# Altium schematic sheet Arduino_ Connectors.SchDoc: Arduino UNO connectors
size A4; Date: 25-FEB-2015; Author: A.B; CompanyName: STMicroelectronics; Address1: 12, Rue Jules HOROWITZ; Address2: 38019 Grenoble; Address3: FRANCE; DocumentNumber: MB1191; Revision: B-02; SheetNumber: 6; SheetTotal: 13; Project: STM32F746G-DISCO
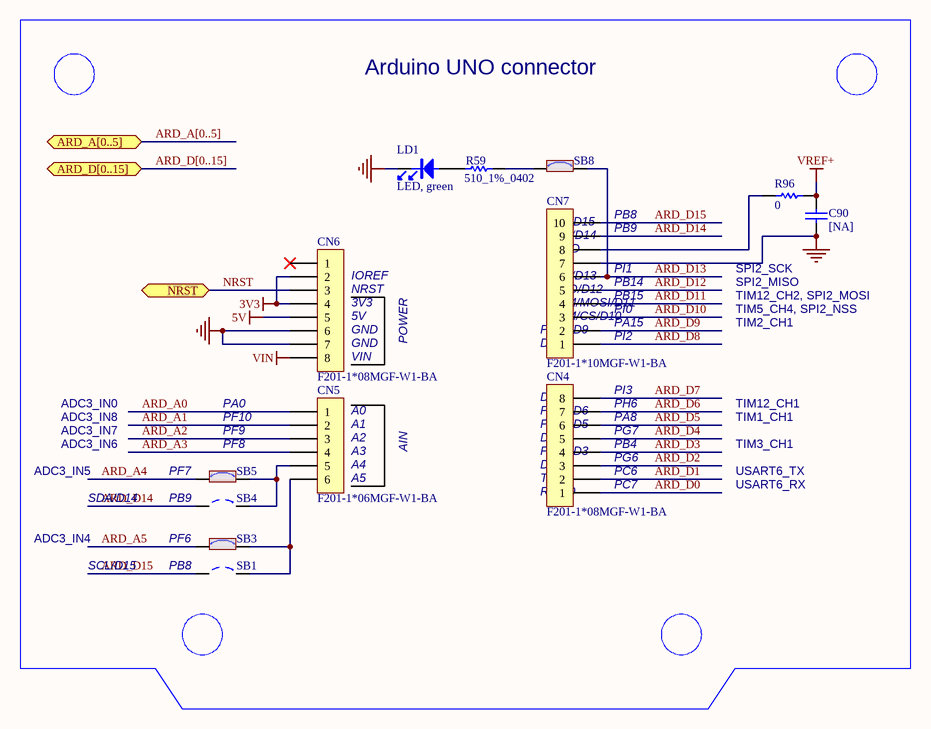
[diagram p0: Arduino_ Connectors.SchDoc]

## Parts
C90  [NA]  [0402C]
CN4  F201-1*08MGF-W1-BA  [F201-1*08MGF-W1-BA]
CN5  F201-1*06MGF-W1-BA  [F201-1*06MGF-W1-BA]
CN6  F201-1*08MGF-W1-BA  [F201-1*08MGF-W1-BA]
CN7  F201-1*10MGF-W1-BA  [F201-1*10MGF-W1-BA]
LD1  LED, green  [0603D]
R59  510_1%_0402  [0402R]
R96  0  [0402R]
SB1  Solder Bridge OFF  [JP2_SMD]  (value not drawn)
SB3  Solder Bridge ON  [JP2_SMD]  (value not drawn)
SB4  Solder Bridge OFF  [JP2_SMD]  (value not drawn)
SB5  Solder Bridge ON  [JP2_SMD]  (value not drawn)
SB8  Solder Bridge ON  [JP2_SMD]  (value not drawn)

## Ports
ARD_A[0..5], ARD_D[0..15], NRST

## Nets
3V3: CN6.2 CN6.4
5V: CN6.5
GND: C90.1 CN6.6 CN6.7 CN7.7 LD1.2
VIN: CN6.8
VREF+: C90.2 R96.2
ARD_A0: CN5.1
ARD_A1: CN5.2
ARD_A2: CN5.3
ARD_A3: CN5.4
ARD_A4: SB5.1
ARD_A5: SB3.1
ARD_D0: CN4.1
ARD_D1: CN4.2
ARD_D2: CN4.3
ARD_D3: CN4.4
ARD_D4: CN4.5
ARD_D5: CN4.6
ARD_D6: CN4.7
ARD_D7: CN4.8
ARD_D8: CN7.1
ARD_D9: CN7.2
ARD_D10: CN7.3
ARD_D11: CN7.4
ARD_D12: CN7.5
ARD_D13: CN7.6 SB8.2
ARD_D14: CN7.9 SB4.1
ARD_D15: CN7.10 SB1.1
NRST: CN6.3 ; port NRST
NetCN5_5: CN5.5 SB4.2 SB5.2
NetCN5_6: CN5.6 SB1.2 SB3.2
NetCN7_8: CN7.8 R96.1
NetLD1_1: LD1.1 R59.1
NetR59_2: R59.2 SB8.1

Not connected (* = marked no-connect by the designer): CN6 1*

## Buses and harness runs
bus ARD_A[0..5] = port ARD_A[0..5]
bus ARD_D[0..15] = port ARD_D[0..15]

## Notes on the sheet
- Arduino UNO connector
- PB8
- (near CN6) IOREF
- (near CN6) NRST
- (near CN7) SDA/D14
- (near CN7) SCL/D15
- (near CN7) SCK/D13
- (near CN7) MISO/D12
- (near CN7) AVDD
- (near CN7) GND
- (near CN7) PB14
- (near CN7) PI1
- (near CN7) PB9
- SPI2_MISO
- SPI2_SCK
- (near CN6) 3V3
- (near CN6) 5V
- (near CN6) GND
- POWER
- (near CN7) D8
- (near CN7) PWM/D9
- (near CN7) PWM/CS/D10
- (near CN7) PWM/MOSI/D11
- (near CN7) PI2
- (near CN7) PA15
- (near CN7) PI0
- (near CN7) PB15
- TIM2_CH1
- TIM5_CH4, SPI2_NSS
- TIM12_CH2, SPI2_MOSI
- ADC3_IN8
- ADC3_IN0
- PA0
- PF10
- (near CN5) A0
- (near CN5) A1
- (near CN6) VIN
- (near CN4) PWM/D5
- (near CN4) PWM/D6
- (near CN4) D7
- (near CN4) PA8
- (near CN4) PH6
- PI3
- TIM1_CH1
- TIM12_CH1
- ADC3_IN5
- ADC3_IN6
- ADC3_IN7
- PF7
- (near SB5) PF9
- (near SB5) PF8
- (near CN5) A2
- (near CN5) A3
- (near CN5) A4
- (near CN5) A5
- AIN
- (near CN4) TX/D1
- (near CN4) D2
- (near CN4) D4
- (near CN4) PWM/D3
- (near CN4) PC6
- (near CN4) PG6
- (near CN4) PB4
- (near CN4) PG7
- (near CN4) PC7
- USART6_RX
- USART6_TX
- TIM3_CH1
- ADC3_IN4
- SDA/D14
- PF6
- PB9
- (near CN4) RX/D0
- SCL/D15

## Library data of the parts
C90 = Cap_NA_0402: Capacitor,NA,0402; Fitted: NO
CN4 CN6 = F201-1*08MGF-W1-BA: Header, 8-Pins, Single row, female SMD; Manuf_1: TOWNES; Manuf_Part_2: SSW-108-22-x-S-VS; Manuf_2: SAMTEC
CN5 = F201-1*06MGF-W1-BA: Header, 6-Pins, Single row, female SMD; Manuf_1: TOWNES; Manuf_Part_2: SSW-106-22-x-S-VS; Manuf_2: SAMTEC
CN7 = F201-1*10MGF-W1-BA: Header, 10-Pins, Single row, female SMD; Manuf_1: TOWNES; Manuf_Part_2: SSW-110-22-x-S-VS; Manuf_2: SAMTEC; Description: Header, 8-Pins, Single row, female SMD
LD1 = LED_green: LED, green, 0603; Manuf_1: everlight; Manuf_Part_1: 19-213SYGC/S530-E2/TR8; Description: LED,green,0603,19-213SYGC/S530-E2/TR8,everlight; ECCN_US/EU: EAR99/NEC
R59 = Res_510_1%_0402: Resistor,510,0402,1%,YAGEO; Manuf_Part_1: RC0402FR-07510L; Value: 510
R96 = Res_0_5%_0402: Resistor,0,0402,5%,YAGEO; Manuf_Part_1: RC0402JR-070RL; Order: 2363467
SB1 SB4 = SB_OFF: Solder: NO
SB3 SB5 SB8 = SB_ON: Solder: YES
